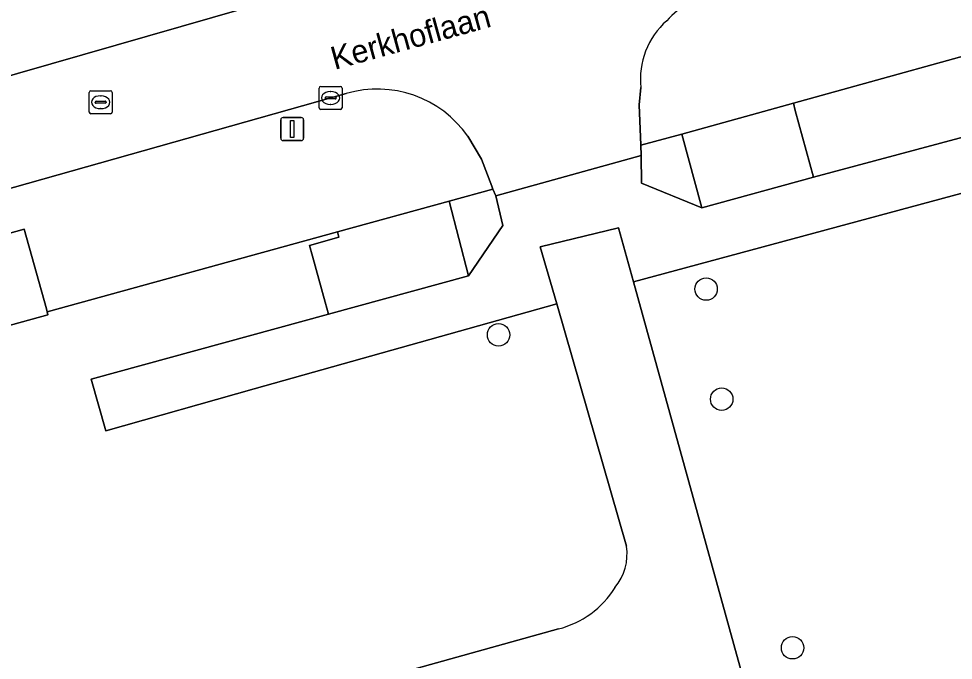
# Model space of a CAD drawing. Extents: x 159053 to 160042, y 380449 to 381423.
# Drawn here: x 159295.18 to 159335.87, y 380919.13 to 380947.08 of the extents above; entities that cross this region are included whole.
import ezdxf

# ---------------------------------------------------------------- set-up
doc = ezdxf.new("R2010")
doc.units = 0
for name, color, linetype in [('IMGEO_Boom', 7, 'Continuous'), ('IMGEO_Groenvoorziening', 7, 'Continuous'), ('IMGEO_Hek', 7, 'Continuous'), ('IMGEO_Kolk', 7, 'Continuous'), ('IMGEO_Lichtmast', 7, 'Continuous'), ('IMGEO_Muur', 7, 'Continuous'), ('IMGEO_Openbare_ruimte_label', 7, 'Continuous'), ('IMGEO_Pand', 7, 'Continuous'), ('IMGEO_Rijbaan_lokaal_open', 7, 'Continuous'), ('IMGEO_Rioolput', 7, 'Continuous'), ('IMGEO_Voetpad_gesloten', 7, 'Continuous'), ('IMGEO_Voetpad_open', 7, 'Continuous')]:
    doc.layers.add(name, color=color, linetype=linetype)

msp = doc.modelspace()

# ---------------------------------------------------------------- linework, layer by layer
at = {"layer": 'IMGEO_Boom'}
for centre in [(159325.108, 380935.304), (159316.074, 380933.311), (159325.786, 380930.505), (159328.873, 380919.674)]:
    msp.add_circle(centre, 0.489, dxfattribs=at)
at = {"layer": 'IMGEO_Groenvoorziening'}
for points in [[(159399.303, 380929.877), (159387.783, 380959.221), (159387.631, 380959.18), (159341.965, 380946.733), (159341.887, 380946.995), (159339.487, 380946.33), (159328.909, 380943.398), (159328.986, 380943.085), (159329.79, 380940.182), (159342.47, 380943.578), (159343.08, 380941.319), (159339.103, 380940.246), (159321.951, 380935.618), (159329.744, 380907.422), (159333.685, 380893.692)], [(159321.643, 380924.103), (159318.603, 380934.661), (159305.427, 380930.949), (159298.973, 380929.13), (159298.341, 380931.373), (159308.663, 380934.21), (159308.52, 380934.729), (159307.969, 380936.734), (159307.839, 380937.207), (159309.118, 380937.568), (159309.054, 380937.802), (159296.42, 380934.314), (159296.448, 380934.184), (159194.979, 380906.143), (159220.802, 380811.72), (159340.546, 380844.447), (159336.09, 380860.753), (159223.202, 380829.611), (159222.554, 380831.933), (159236.663, 380835.876), (159259.546, 380842.271), (159305.824, 380855.205), (159335.776, 380863.627), (159336.487, 380863.886)], [(159320.026, 380918.376), (159301.8, 380913.396), (159279.05, 380906.957), (159221.084, 380890.807), (159206.081, 380886.572), (159205.42, 380889.01), (159218.379, 380892.522), (159318.679, 380920.497)]]:
    msp.add_lwpolyline(points, dxfattribs=at)
for points in [[(159324.047, 380942.045), (159322.269, 380941.577), (159322.284, 380941.127), (159322.298, 380939.923), (159324.925, 380938.846)], [(159315.952, 380939.363), (159315.828, 380939.657), (159313.921, 380939.13), (159314.761, 380935.886), (159316.261, 380938.071)], [(159296.448, 380934.184), (159296.42, 380934.314), (159296.393, 380934.435), (159295.42, 380937.918), (159199.726, 380911.13), (159195.395, 380909.913), (159194.248, 380908.271), (159194.979, 380906.143)]]:
    msp.add_lwpolyline(points, close=True, dxfattribs=at)
for centre, radius, start, end in [((159319.361, 380923.763), 2.307, 320.5267, 8.4643), ((159317.694, 380924.43), 4.055, 284.062, 328.2579)]:
    msp.add_arc(centre, radius, start, end, dxfattribs=at)
at = {"layer": 'IMGEO_Hek'}
for points in [[(159296.448, 380934.184), (159296.42, 380934.314)], [(159194.979, 380906.143), (159296.448, 380934.184)]]:
    msp.add_lwpolyline(points, dxfattribs=at)
at = {"layer": 'IMGEO_Kolk'}
for p, q in [((159308.26, 380943.203), (159308.26, 380944.055)), ((159308.335, 380944.129), (159309.187, 380944.129)), ((159309.261, 380944.055), (159309.261, 380943.203)), ((159308.562, 380943.672), (159308.96, 380943.672)), ((159308.748, 380943.909), (159308.773, 380943.909)), ((159308.519, 380943.623), (159308.519, 380943.635)), ((159308.957, 380943.586), (159308.559, 380943.586)), ((159308.771, 380943.349), (159308.746, 380943.349)), ((159309.003, 380943.635), (159309.003, 380943.623)), ((159309.187, 380943.129), (159308.335, 380943.129))]:
    msp.add_line(p, q, dxfattribs=at)
for points in [[(159308.26, 380943.203), (159308.26, 380944.055)], [(159308.335, 380944.129), (159309.187, 380944.129)], [(159309.261, 380944.055), (159309.261, 380943.203)], [(159309.187, 380943.129), (159308.335, 380943.129)]]:
    msp.add_lwpolyline(points, dxfattribs=at)
for centre, radius, start, end in [((159308.337, 380944.053), 0.0765, 91.552, 178.448), ((159308.337, 380944.053), 0.0765, 91.552, 178.448), ((159309.185, 380944.053), 0.0765, 1.552, 88.448), ((159309.185, 380944.053), 0.0765, 1.552, 88.448), ((159308.559, 380943.632), 0.0403, 85.8775, 175.7526), ((159308.964, 380943.634), 0.0386, 1.7309, 96.639), ((159308.556, 380943.622), 0.0366, 178.938, 274.7102), ((159308.96, 380943.629), 0.043, 264.8664, 352.4533), ((159308.337, 380943.205), 0.0765, 181.552, 268.448), ((159308.337, 380943.205), 0.0765, 181.552, 268.448), ((159309.185, 380943.205), 0.0765, 271.552, 358.448), ((159309.185, 380943.205), 0.0765, 271.552, 358.448)]:
    msp.add_arc(centre, radius, start, end, dxfattribs=at)
for centre, major_axis, ratio, start_param, end_param in [((159308.747, 380943.629), (-0.387, 0.002), 0.722429, 4.712389, 7.853982), ((159308.772, 380943.629), (-0.39, 0.002), 0.717154, 1.570796, 4.712389)]:
    msp.add_ellipse(centre, major_axis=major_axis, ratio=ratio, start_param=start_param, end_param=end_param, dxfattribs=at)
at = {"layer": 'IMGEO_Lichtmast'}
for p, q in [((159306.593, 380941.874), (159306.593, 380942.674)), ((159306.593, 380942.674), (159306.593, 380941.874)), ((159306.693, 380942.774), (159307.483, 380942.774)), ((159307.483, 380942.774), (159306.693, 380942.774)), ((159307.583, 380942.674), (159307.583, 380941.874)), ((159307.583, 380941.874), (159307.583, 380942.674)), ((159307.483, 380941.774), (159306.693, 380941.774)), ((159306.693, 380941.774), (159307.483, 380941.774))]:
    msp.add_line(p, q, dxfattribs=at)
msp.add_lwpolyline([(159307.013, 380942.649), (159307.163, 380942.649), (159307.163, 380941.899), (159307.013, 380941.899), (159307.013, 380942.649)], dxfattribs=at)
for centre, start, end in [((159306.693, 380942.674), 90, 180), ((159306.693, 380942.674), 90, 180), ((159307.483, 380942.674), 0, 90), ((159307.483, 380942.674), 360, 90), ((159306.693, 380941.874), 180, 270), ((159306.693, 380941.874), 180, 270), ((159307.483, 380941.874), 270, 0), ((159307.483, 380941.874), 270, 0)]:
    msp.add_arc(centre, 0.1, start, end, dxfattribs=at)
at = {"layer": 'IMGEO_Muur'}
for points in [[(159341.887, 380946.995), (159328.909, 380943.398)], [(159324.047, 380942.045), (159328.909, 380943.398)], [(159324.047, 380942.045), (159322.269, 380941.577)], [(159313.921, 380939.13), (159315.828, 380939.657)], [(159313.921, 380939.13), (159309.054, 380937.802)], [(159296.42, 380934.314), (159309.054, 380937.802)]]:
    msp.add_lwpolyline(points, dxfattribs=at)
at = {"layer": 'IMGEO_Pand'}
for points in [[(159328.986, 380943.085), (159328.909, 380943.398), (159324.047, 380942.045), (159324.925, 380938.846), (159329.79, 380940.182)], [(159313.921, 380939.13), (159309.054, 380937.802), (159309.118, 380937.568), (159307.839, 380937.207), (159307.969, 380936.734), (159308.52, 380934.729), (159308.663, 380934.21), (159314.761, 380935.886)]]:
    msp.add_lwpolyline(points, close=True, dxfattribs=at)
at = {"layer": 'IMGEO_Rijbaan_lokaal_open'}
for points in [[(159305.085, 380947.551), (159289.451, 380943.067), (159271.799, 380938.174), (159273.09, 380933.625), (159291.177, 380938.669), (159309.441, 380943.822)], [(159289.451, 380943.067), (159305.085, 380947.551)], [(159314.732, 380941.958), (159315.331, 380940.961), (159315.774, 380939.786), (159315.828, 380939.657), (159315.952, 380939.363), (159322.284, 380941.127), (159322.269, 380941.577), (159322.199, 380943.328), (159322.268, 380944.078)]]:
    msp.add_lwpolyline(points, dxfattribs=at)
for centre, radius, start, end in [((159326.425, 380944.183), 4.136, 102.5515, 137.1635), ((159325.649, 380944.45), 3.402, 131.5746, 186.2794), ((159310.795, 380939.225), 4.792, 34.7686, 106.417)]:
    msp.add_arc(centre, radius, start, end, dxfattribs=at)
at = {"layer": 'IMGEO_Rioolput'}
for p, q in [((159298.252, 380943.017), (159298.252, 380943.869)), ((159298.327, 380943.943), (159299.179, 380943.943)), ((159298.74, 380943.723), (159298.765, 380943.723)), ((159299.253, 380943.869), (159299.253, 380943.017)), ((159298.511, 380943.437), (159298.511, 380943.449)), ((159298.949, 380943.4), (159298.551, 380943.4)), ((159298.554, 380943.486), (159298.952, 380943.486)), ((159298.995, 380943.449), (159298.995, 380943.437)), ((159299.179, 380942.943), (159298.327, 380942.943)), ((159298.763, 380943.163), (159298.738, 380943.163))]:
    msp.add_line(p, q, dxfattribs=at)
for points in [[(159298.252, 380943.017), (159298.252, 380943.869)], [(159298.327, 380943.943), (159299.179, 380943.943)], [(159299.253, 380943.869), (159299.253, 380943.017)], [(159299.179, 380942.943), (159298.327, 380942.943)]]:
    msp.add_lwpolyline(points, dxfattribs=at)
for centre, radius, start, end in [((159298.329, 380943.867), 0.0765, 91.552, 178.448), ((159298.329, 380943.867), 0.0765, 91.552, 178.448), ((159299.177, 380943.867), 0.0765, 1.552, 88.448), ((159299.177, 380943.867), 0.0765, 1.552, 88.448), ((159298.551, 380943.446), 0.0403, 85.8775, 175.7526), ((159298.548, 380943.436), 0.0366, 178.938, 274.7102), ((159298.952, 380943.443), 0.043, 264.8664, 352.4533), ((159298.956, 380943.448), 0.0386, 1.7309, 96.639), ((159298.329, 380943.019), 0.0765, 181.552, 268.448), ((159298.329, 380943.019), 0.0765, 181.552, 268.448), ((159299.177, 380943.019), 0.0765, 271.552, 358.448), ((159299.177, 380943.019), 0.0765, 271.552, 358.448)]:
    msp.add_arc(centre, radius, start, end, dxfattribs=at)
for centre, major_axis, ratio, start_param, end_param in [((159298.739, 380943.443), (-0.387, 0.002), 0.722429, 4.712389, 7.853982), ((159298.764, 380943.443), (-0.39, 0.002), 0.717154, 1.570796, 4.712389)]:
    msp.add_ellipse(centre, major_axis=major_axis, ratio=ratio, start_param=start_param, end_param=end_param, dxfattribs=at)
at = {"layer": 'IMGEO_Voetpad_gesloten'}
for points in [[(159333.685, 380893.692), (159329.744, 380907.422), (159321.951, 380935.618), (159321.301, 380937.971), (159317.888, 380937.146), (159318.603, 380934.661), (159321.643, 380924.103)], [(159318.679, 380920.497), (159218.379, 380892.522), (159205.42, 380889.01), (159206.081, 380886.572), (159221.084, 380890.807), (159279.05, 380906.957), (159301.8, 380913.396), (159320.026, 380918.376)]]:
    msp.add_lwpolyline(points, dxfattribs=at)
for centre, radius, start, end in [((159319.361, 380923.763), 2.307, 320.5267, 8.4643), ((159317.694, 380924.43), 4.055, 284.062, 328.2579)]:
    msp.add_arc(centre, radius, start, end, dxfattribs=at)
at = {"layer": 'IMGEO_Voetpad_open'}
for points in [[(159322.268, 380944.078), (159322.199, 380943.328), (159322.269, 380941.577), (159324.047, 380942.045), (159328.909, 380943.398), (159339.487, 380946.33), (159338.456, 380950.454)], [(159309.441, 380943.822), (159291.177, 380938.669), (159273.09, 380933.625), (159270.392, 380932.872), (159251.048, 380927.477), (159212.83, 380916.824), (159205.315, 380914.615), (159202.625, 380913.824), (159202.183, 380913.694), (159193.225, 380911.241), (159191.928, 380910.886), (159183.581, 380908.568), (159183.081, 380908.43), (159184.215, 380904.409), (159186.407, 380905.035), (159191.171, 380906.353), (159191.665, 380904.574), (159194.248, 380908.271), (159195.395, 380909.913), (159199.726, 380911.13), (159295.42, 380937.918)], [(159295.42, 380937.918), (159296.393, 380934.435), (159296.42, 380934.314), (159309.054, 380937.802), (159313.921, 380939.13), (159315.828, 380939.657), (159315.774, 380939.786), (159315.331, 380940.961), (159314.732, 380941.958)]]:
    msp.add_lwpolyline(points, dxfattribs=at)
msp.add_lwpolyline([(159322.284, 380941.127), (159315.952, 380939.363), (159316.261, 380938.071), (159314.761, 380935.886), (159308.663, 380934.21), (159298.341, 380931.373), (159298.973, 380929.13), (159305.427, 380930.949), (159318.603, 380934.661), (159317.888, 380937.146), (159321.301, 380937.971), (159321.951, 380935.618), (159339.103, 380940.246), (159343.08, 380941.319), (159342.47, 380943.578), (159329.79, 380940.182), (159324.925, 380938.846), (159322.298, 380939.923)], close=True, dxfattribs=at)
for centre, radius, start, end in [((159326.425, 380944.183), 4.136, 102.5515, 137.1635), ((159325.649, 380944.45), 3.402, 131.5746, 186.2794), ((159310.795, 380939.225), 4.792, 34.7686, 106.417)]:
    msp.add_arc(centre, radius, start, end, dxfattribs=at)

# ---------------------------------------------------------------- texts
at = {"layer": 'IMGEO_Openbare_ruimte_label'}
msp.add_text('Kerkhoflaan', height=1, rotation=15.426, dxfattribs=at).set_placement((159308.934, 380944.849))

doc.saveas('drawing.dxf')
